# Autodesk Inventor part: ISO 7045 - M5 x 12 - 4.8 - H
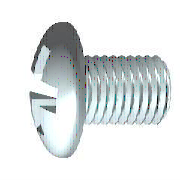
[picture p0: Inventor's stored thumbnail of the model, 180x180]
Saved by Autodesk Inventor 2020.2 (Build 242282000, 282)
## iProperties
Manager: www.cadconsulting.pl
Company: Fabian Stasiak CAD Consulting
Created: 2006-02
Part Number: ISO 7045 - M5 x 12 - 4.8 - H
Material: Stal, miękka
Description: Śruba ze łbem walcowym wypukłym z wgłębieniem krzyżowym
Document SubType Name: Modeling
Standard: ISO 7045
Designer: F.Stasiak
Standards Organization: DIN
Language: pl-PL
Size Designation: M5 x 12 - 4.8 - H
Categories: <MemberInstance><Categories><Category DisplayName="Mocowania" InternalName="e4da775c-781d-43d5-af7c-5136215cf5a6" Mnemonic="FSTN"><Category DisplayName="Śruby"
Density: 1 g/cm^3
Appearance: Stal
Author: F.Stasiak
Subject: Zbiór ćwiczeń. Autodesk Inventor 2020. Kurs podstawowy
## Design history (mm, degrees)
node "Bryła1"
node "Korpusy bryłowe"
node "Korpusy powierzchniowe"
sketch "Szkic1"
  geometry: L1 (12, 0)-(12, 2.5); L2 (12, 2.5)-(1.6, 2.5); L3 (3.962, 5.08)-(3.962, 5.08); L4 (-3.7, 0)-(-3.7, 4.621); L5 (-3.367, 2.284)-(-1.526, 1.366); L6 (-1.526, 1.366)-(-0.8, 0); L7 (-0.8, 0)-(12, 0); L8 (-5.674, 0)-(16.82, 0) reference; L9 (0, -0.508)-(0, 6.604) reference; L10 (-3.367, 2.284)-(-3.7, 2.45); L11 (-2.193, 4.673)-(-3.7, 4.621); L12 (-2.193, 4.673)-(0, 4.75); L13 (0, 4.75)-(0, 2.283); L14 (0, 2.283)-(1.109, 2.283); L15 (1.109, 2.283)-(1.6, 2.5); L16 (1.6, 2.5)-(0, 2.5); A1 r 8 centre (4.3, 0) between (-2.193, 4.673) and (-3.7, 0)
  constraints: 28 end point, 5 point on line, 4 collinear, 4 point on circle, 3 parallel, 2 perpendicular, 1 centre point, 1 horizontal, 1 tangent
  dimensions: "d1" = 5 diameter of L2 L7 (= GD); "d2" = 2.9 distance from line of L6.end L4 (= STI); "d11" = 4.9 diameter of L10.end L7 (= SDM); "d12" = 62 deg angle of L6 L7; "d13" = 26.5 deg angle of L5 L7; "d17" = 9.5 diameter of L12.end L7 (= KOD); "d19" = 2 deg angle of L12 L7 (= KEWI); "d20" = 3.7 distance between parallel lines of L4 L13 (= KOH); "d21" = 8 radius of A1 (= KR); "d23" = 4.56699 diameter of L14 L7 (= BDM); "d24" = 10.4 distance of L1.end L2.end (= GEL); "d25" = 0.49076 horizontal distance of L14.end L2.end (= GAL); "d28" = 12 distance between parallel lines of L1 L13 (= NLG)
revolve "Bryła" stored, may be unused: angle "d18" = 90 deg
node "IDS_WORKPLANE{1}"
sketch "Szkic2"
  geometry: L1 (-5.608, 0)-(7.477, 0) reference; L2 (0, -5.608)-(0, 7.477) reference; L3 (0, 2.45)-(0, 0); L4 (0, 0)-(2.45, 0); L5 (0, 0)-(3.305, 3.305); L6 (0.415, 2.415)-(0.426, 0.744); L7 (2.415, 0.415)-(0.744, 0.426); L8 (0.415, -2.415)-(0.426, -0.744); L9 (2.415, -0.415)-(0.744, -0.426); L10 (-0.415, 2.415)-(-0.426, 0.744); L11 (-2.415, 0.415)-(-0.744, 0.426); L12 (-2.415, -0.415)-(-0.744, -0.426); L13 (-0.415, -2.415)-(-0.426, -0.744); A1 r 0.735 centre (0, 0) between (0.735, 0) and (0, 0.735); A2 r 2.45 centre (0, 0) between (2.45, 0) and (2.415, 0.415); A3 r 2.45 centre (0, 0) between (0.415, 2.415) and (0, 2.45); A4 r 2.45 centre (0, 0) between (2.415, 0.415) and (0.415, 2.415); A5 r 2.45 centre (0, 0) between (0, -2.45) and (0.415, -2.415); A6 r 2.45 centre (0, 0) between (0.415, -2.415) and (2.415, -0.415); A7 r 2.45 centre (0, 0) between (2.415, -0.415) and (2.45, 0); A8 r 2.45 centre (0, 0) between (-2.415, 0.415) and (-2.45, 0); A9 r 2.45 centre (0, 0) between (-0.415, 2.415) and (-2.415, 0.415); A10 r 2.45 centre (0, 0) between (0, 2.45) and (-0.415, 2.415); A11 r 2.45 centre (0, 0) between (-2.45, 0) and (-2.415, -0.415); A12 r 2.45 centre (0, 0) between (-2.415, -0.415) and (-0.415, -2.415); A13 r 2.45 centre (0, 0) between (-0.415, -2.415) and (0, -2.45); A14 r 0.858 centre (0, 0) between (0.858, 0) and (0, 0.858); A15 r 0.321 centre (0.746, 0.746) between (0.426, 0.744) and (0.744, 0.426); A16 r 0.321 centre (0.746, -0.746) between (0.744, -0.426) and (0.426, -0.744); A17 r 0.321 centre (-0.746, 0.746) between (-0.744, 0.426) and (-0.426, 0.744); A18 r 0.321 centre (-0.746, -0.746) between (-0.426, -0.744) and (-0.744, -0.426); 1 further point
  constraints: 38 point on circle, 22 end point, 19 symmetric about line, 18 centre point, 4 coincident, 3 collinear, 3 point on line, 3 tangent, 1 perpendicular, 21 other
  dimensions: "d4" = 45 deg angle of L5 L4; "d5" = 1.47 diameter of A1 (= 0.3 x SDM); "d6" = 4.9 diameter of A4 (= SDM); "d7" = 0.415 distance from line of L6.start L3 (= 0.5 x SBR); "d14" = 1.715 diameter of A14 (= 0.35 x SDM)
extrude "Szczelina" join sketch "Szkic2" taper "d15" = 5 deg; stored distance "d54" = 10
revolve "Wycięcie" stored, may be unused: angle "d56" = 90 deg
fillet "Zaokrąglenie1" dims "d29" = 1.6 (= RR)
fillet "Zaokrąglenie2" dims "d16" = 0.166 (= 0.2 x SBR)
feature "Gwint" dims "d8" = 10.4 (= GEL), "d9" = 0
chamfer "Faza1" distance "d26" = 0.49076 (= -0.5 x SPD + 0.5 x GD); stored, may be unused: second distance "d27" = 0.49086 (computed from GUL), angle "d78" = 45 deg
workplane "Work Plane3"
other parameters: "GD" = 5 [user parameter; used in 2 equation terms], "NLG" = 12 [user parameter; used in 1 equation term], "GEL" = 10.4 [user parameter; used in 2 equation terms], "KOD" = 9.5 [user parameter; used in 1 equation term], "KOH" = 3.7 [user parameter; used in 2 equation terms], "SDM" = 4.9 [user parameter; used in 4 equation terms], "STI" = 2.9 [user parameter; used in 1 equation term], "SBR" = 0.83 [user parameter; used in 2 equation terms], "GAL" = 0.49076 (= 0.61345 x PTC) [user parameter; used in 1 equation term], "SPD" = 4.01848 (= NND - 1.2269 x PTC) [user parameter; used in 1 equation term], "KEWI" = 2 deg [user parameter; used in 1 equation term], "d3" = -3.7 (= -KOH), "d10" = 0, "KR" = 8 [user parameter; used in 1 equation term], "BDM" = 4.56699 [user parameter; used in 1 equation term], "GUL" = 0.49076 (= 0.61345 x PTC) [user parameter; used in 1 equation term], "RR" = 1.6 [user parameter; used in 1 equation term], "d79" = 0, "d80" = 0, "PTC" = 0.8 [user parameter; used in 5 equation terms], "THREADDIA" = 5 [user parameter; used in 1 equation term], "TOA" = 30 deg [user parameter], "TPU" = 12.5 (computed from PTC) [user parameter], "NND" = 5 [user parameter; used in 1 equation term], "GD1" = 4.01848 (= THREADDIA - 1.2269 x PTC) [user parameter]
